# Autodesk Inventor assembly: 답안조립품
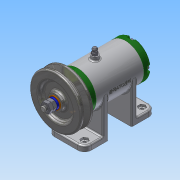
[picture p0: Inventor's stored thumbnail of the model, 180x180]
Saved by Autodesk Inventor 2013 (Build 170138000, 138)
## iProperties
Created: 2017-02
Part Number: 답안조립품
Document SubType Name: Assembly
Designer: Administrator
Author: Administrator
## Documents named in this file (16)
- C:\Users\Administrator\Desktop\470207V1020\답안조립품.iam
- C:\Users\Administrator\Desktop\470207V1020\본체.ipt
- C:\Users\Administrator\Desktop\470207V1020\베어링 15 x 32 x 9.ipt
- C:\Users\Administrator\Desktop\470207V1020\뒤커버.ipt
- C:\Users\Administrator\Desktop\470207V1020\앞커버.ipt
- C:\Users\Administrator\Desktop\470207V1020\오일 실 15 25 7.ipt
- C:\Users\Administrator\Desktop\470207V1020\볼트 M4 x 12.ipt
- C:\Users\Administrator\Desktop\470207V1020\축.ipt
- C:\Users\Administrator\Desktop\470207V1020\키 3 x 3 x 12.ipt
- C:\Users\Administrator\Desktop\470207V1020\V벨트풀리.ipt
- C:\Users\Administrator\Desktop\470207V1020\와셔 8x17.ipt
- C:\Users\Administrator\Desktop\470207V1020\스프링와셔 8.ipt
- C:\Users\Administrator\Desktop\470207V1020\너트 M 8.ipt
- C:\Users\Administrator\Desktop\470207V1020\와셔 6x11.5.ipt
- C:\Users\Administrator\Desktop\470207V1020\볼트 M 6 x 8.ipt
- C:\Users\Administrator\Desktop\470207V1020\니플 M 6 x 0.75.ipt
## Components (11 placed, 3 different names)
1. KS B 2023 6002 - 15 x 32 x 9:1
2. KS B 2023 6002 - 15 x 32 x 9:2
3. V벨트풀리:1 — 각도:2
4. ISO 4762 M4 x 12:1
5. ISO 4762 M4 x 12:3
6. ISO 4762 M4 x 12:4
7. ISO 4762 M4 x 12:5
8. ISO 4762 M4 x 12:2
9. ISO 4762 M4 x 12:6
10. ISO 4762 M4 x 12:7
11. ISO 4762 M4 x 12:8
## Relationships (1: Angle 1)
- 각도:2 [Angle]: V벨트풀리:1
